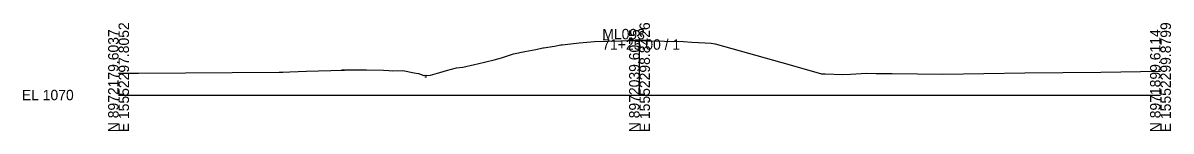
# Model space of a CAD drawing. Extents: x -26 to 14283, y -10 to 28.
# Drawn here: x 12974.3 to 13282.8, y -9.7 to 19.4 of the extents above; entities that cross this region are included whole.
import ezdxf

# ---------------------------------------------------------------- set-up
doc = ezdxf.new("R2010")
doc.units = 0
for name, color, linetype in [('dsnGeopakCellCrossSection', 7, 'Continuous'), ('dsnXsExistingGround', 7, 'Continuous'), ('SurSurveyPoints', 7, 'Continuous')]:
    doc.layers.add(name, color=color, linetype=linetype)

msp = doc.modelspace()

# ---------------------------------------------------------------- linework, layer by layer
at = {"layer": 'dsnGeopakCellCrossSection'}
for p, q in [((13140, 0), (13140, 15)), ((13000, 0), (13140, 0)), ((13140, 0), (13280, 0))]:
    msp.add_line(p, q, dxfattribs=at)
at = {"layer": 'dsnXsExistingGround'}
msp.add_lwpolyline([(13000, 5.9), (13005.39, 5.89), (13043.17, 6.15), (13043.64, 6.16), (13043.75, 6.16), (13050.47, 6.38), (13060.27, 6.73), (13060.74, 6.73), (13060.96, 6.76), (13066.64, 6.74), (13071.21, 6.72), (13072.65, 6.56), (13073.62, 6.54), (13076.43, 6.57), (13079.46, 5.96), (13080.6, 5.83), (13082.02, 5.23), (13082.54, 5.32), (13082.76, 5.27), (13083.87, 5.37), (13086.36, 6.03), (13088.1, 6.6), (13090.85, 7.28), (13092.48, 7.5), (13095.68, 8.26), (13096.45, 8.44), (13100.92, 9.5), (13102.91, 9.98), (13106.09, 11.08), (13109.15, 11.73), (13112.1, 12.27), (13114.04, 12.66), (13114.22, 12.69), (13117.13, 13.19), (13118.84, 13.48), (13119.19, 13.53), (13120.01, 13.61), (13123.8, 14.01), (13126.93, 14.33), (13127.88, 14.43), (13134.97, 14.56), (13139.99, 14.65), (13141.61, 14.62), (13151.85, 14.38), (13154.09, 14.26), (13157.63, 14.08), (13159.22, 13.92), (13160.33, 13.81), (13180.49, 8.1), (13188.87, 5.73), (13189.88, 5.71), (13194.63, 5.56), (13196.7, 5.65), (13201.04, 5.85), (13203.59, 5.82), (13207.92, 5.78), (13221.53, 5.65), (13243.53, 5.97), (13263.99, 6.18), (13280, 6.44)], dxfattribs=at)
at = {"layer": 'SurSurveyPoints'}
for points in [[(13060.73, 6.7), (13059.88, 6.7)], [(13043.18, 6.16), (13044.11, 6.16)], [(13082.76, 4.85), (13082.32, 4.85)]]:
    msp.add_lwpolyline(points, dxfattribs=at)

# ---------------------------------------------------------------- texts
msp.add_text('-', height=0.0001).set_placement((13000, 0))
at = {"layer": 'dsnGeopakCellCrossSection'}
for s, p in [('E 15552297.8052', (13002.8, -10)), ('E 15552298.8426', (13142.8, -10)), ('E 15552299.8799', (13282.8, -10)), ('N 8972179.6037', (13000, -10)), ('N 8972039.6075', (13140, -10)), ('N 8971899.6114', (13280, -10))]:
    msp.add_text(s, height=2.8, rotation=90, dxfattribs=at).set_placement(p)
for s, p in [('ML093', (13130, 15)), ('71+25.00 / 1', (13130, 12.2)), ('EL 1070', (12974, -1.4))]:
    msp.add_text(s, height=2.8, dxfattribs=at).set_placement(p)

doc.saveas('drawing.dxf')
